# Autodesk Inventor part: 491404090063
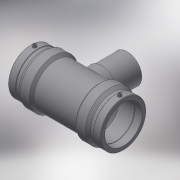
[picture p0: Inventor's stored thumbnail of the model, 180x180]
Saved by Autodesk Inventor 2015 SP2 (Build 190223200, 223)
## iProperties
Created: 2017-06
Part Number: 491404090063
Material: Generic
Description: PLASSON REDUCING TEE 90x63x90
Document SubType Name: Modeling
Designer: KIM
Mass: 959.049 g
Surface Area: 2119.36 cm^2
Volume: 959.049 cm^3
Density: 1 g/cm^3
Appearance: Default
Author: KIM
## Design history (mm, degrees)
derived "491404.ipt"
feature "Solid1::491404.ipt"
tag "TaggingFeature1"
body "Solid1"
other parameters: "d0" = 294, "d2" = 113, "d3" = 68, "d4" = 58.8, "d5" = 101.7, "d6" = 85.5, "d8" = 168 deg, "d10" = 27.2, "d11" = 9.06667, "d13" = 294, "d14" = 17.6296, "d17" = 81, "d19" = 3.52592, "d20" = 168 deg, "d22" = 105.09, "d23" = 113, "d25" = 135 deg, "d26" = 205.8, "d29" = 71, "d30" = 15, "d31" = 117.6, "d34" = 5 deg, "d35" = 15, "d39" = 5 deg, "d41" = 4, "d42" = 14, "d43" = 0, "d45" = 4, "d46" = 6, "d47" = 0, "d48" = -124, "d49" = 63, "d51" = 0, "d52" = 50.4, "d54" = 0, "d55" = 101.7, "d56" = 113, "d57" = 102.9, "d58" = 135 deg, "d59" = 68, "d60" = 68, "d61" = 135 deg, "d62" = 124, "d72" = 133.77, "d73" = 66.885, "d74" = -124, "d75" = 66.15, "d77" = 0, "d78" = 50.4, "d80" = 0, "d81" = 63, "d82" = 67.5, "d83" = 0, "d84" = 3, "d85" = 0, "d86" = 22.66667, "d87" = 102.9882, "d88" = 9.06667, "d89" = 3, "d90" = 0, "L_" = 294, "L_1" = 68, "D_" = 113, "A_" = 71, "d_2" = 12, "H_" = 124, "d_1" = 63
